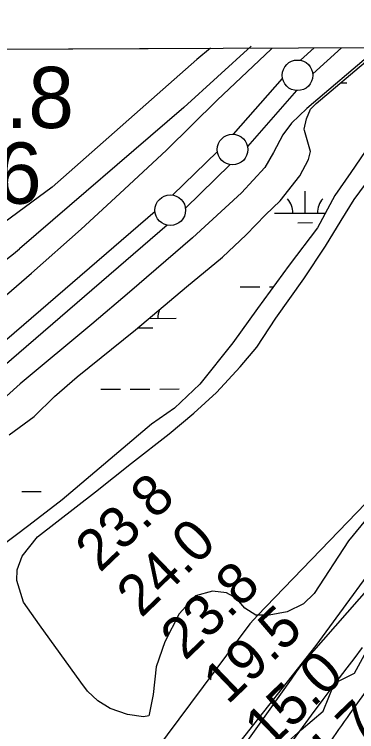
# Model space of a CAD drawing. Extents: x 3424494 to 3462436, y 522220 to 547718.
# Drawn here: x 3447583 to 3448142, y 544764 to 545936 of the extents above; entities that cross this region are included whole.
import ezdxf

# ---------------------------------------------------------------- set-up
doc = ezdxf.new("R2010")
doc.units = 0
for name, color, linetype in [('V-GRID-FRAM', 7, 'Continuous'), ('V-LEVE-TOET', 7, 'Continuous'), ('V-RIVR-EDGE', 7, 'Continuous'), ('V-RIVR-RANG', 7, 'Continuous'), ('V-ROAD-CNTR', 7, 'Continuous'), ('V-SITE-VEGE', 7, 'Continuous'), ('V-SURV-IDEN', 7, 'Continuous'), ('V-SURV-LINE', 7, 'Continuous'), ('V-TOPO-DPTH', 7, 'Continuous'), ('V-TOPO-MINR', 7, 'Continuous'), ('V-WETL-SWMP', 7, 'Continuous')]:
    doc.layers.add(name, color=color, linetype=linetype)

msp = doc.modelspace()

# ---------------------------------------------------------------- linework, layer by layer
at = {"layer": 'V-GRID-FRAM'}
for points in [[(3428547.8, 545793.2), (3460200.7, 545935.9)], [(3428547.8, 545793.2), (3451467.1, 545896.5)]]:
    msp.add_lwpolyline(points, dxfattribs=at)
at = {"layer": 'V-LEVE-TOET'}
for points in [[(3446734.1, 544761.9), (3446808.8, 544826.2), (3446895.8, 544902.1), (3446976.1, 544971.6), (3447070.3, 545048.6), (3447166.5, 545134), (3447247.2, 545207.1), (3447327, 545278.2), (3447384.7, 545328.2), (3447416.5, 545354), (3447439.5, 545375.9), (3447451.8, 545384.6), (3447464.5, 545393.7), (3447537.3, 545449.3), (3447610.8, 545513.3), (3447692.3, 545585.1), (3447755.1, 545643.5), (3447831.4, 545714.2), (3447914, 545795.6), (3448001.9, 545879), (3448003.7, 545880.9)], [(3448177, 545881.7), (3448171.9, 545876.8), (3448060.2, 545782.3), (3448035.6, 545758.1), (3448021.3, 545739), (3448005.8, 545710.4), (3447991.9, 545685.8), (3447953.7, 545644.5), (3447873.8, 545571), (3447770.9, 545482), (3447709.3, 545429.6), (3447592.4, 545332.3), (3447519.7, 545267.2), (3447440.2, 545198.9), (3447431.5, 545190.1), (3447416.4, 545175.4), (3447410.4, 545170.3), (3447402.1, 545163.9), (3447381.8, 545146.8), (3447242.3, 545026.9), (3447093.7, 544898.2), (3446965.7, 544788.2), (3446817.5, 544663.1)]]:
    msp.add_lwpolyline(points, dxfattribs=at)
at = {"layer": 'V-RIVR-EDGE'}
msp.add_spline([(3449024.5, 545885.5), (3449019.3, 545873.5), (3449011.8, 545864), (3448999, 545850.5), (3448985, 545836.1), (3448976.3, 545824.5), (3448965.5, 545808.1), (3448951.4, 545790.8), (3448930.4, 545766.9), (3448908.8, 545733.6), (3448893.9, 545712.1), (3448877.4, 545692), (3448858.8, 545671.4), (3448838.9, 545650.8), (3448829.8, 545641), (3448822, 545628.2), (3448802.1, 545605.2), (3448785.1, 545578.4), (3448774, 545564.8), (3448769, 545560.7), (3448761.1, 545553.7), (3448753.7, 545540.1), (3448748.7, 545530.6), (3448741.3, 545522), (3448732.6, 545514.6), (3448730.5, 545510.9), (3448729.7, 545504.3), (3448730.5, 545498.5), (3448726.4, 545491.9), (3448714, 545480.8), (3448695.8, 545464.4), (3448686.3, 545455.7), (3448680.1, 545452.4), (3448668.5, 545431.4), (3448642, 545397.3), (3448623, 545372.2), (3448598.5, 545341.7), (3448586.1, 545326.9), (3448567.5, 545299.7), (3448554.3, 545276.7), (3448543.5, 545261), (3448535.2, 545255.3), (3448529.4, 545249.1), (3448514.6, 545229.3), (3448492.2, 545191.9), (3448480.6, 545178.7), (3448457.5, 545153.6), (3448442.1, 545135.1), (3448424.4, 545110.8), (3448410.3, 545090.6), (3448392.9, 545075.8), (3448377.6, 545060.6), (3448361.1, 545040.4), (3448350.7, 545027.7), (3448339.1, 545005.8), (3448331.3, 544993.5), (3448317.6, 544978.7), (3448303.6, 544960.5), (3448289.9, 544948.2), (3448280, 544931.7), (3448265.1, 544908.3), (3448249.8, 544884), (3448245.2, 544876.6), (3448244.4, 544872.9), (3448244.4, 544867.1), (3448242.3, 544863.4), (3448237.7, 544861.3), (3448234.4, 544856.8), (3448231.1, 544846.5), (3448224.9, 544842), (3448220.4, 544838.3), (3448221.6, 544830.8), (3448219.1, 544824.3), (3448214.5, 544819.7), (3448208.8, 544818.9), (3448205.5, 544816.4), (3448194.7, 544800.4), (3448196.4, 544802), (3448189.7, 544791.3), (3448179.4, 544775.7), (3448174, 544768.7), (3448167.4, 544757.2), (3448157.4, 544744.4), (3448145.4, 544730.8), (3448135.1, 544715.2), (3448124.8, 544701.2), (3448119.4, 544699.9), (3448113.2, 544693), (3448107.4, 544682.7), (3448106.1, 544678.9), (3448100.3, 544665.8), (3448092.9, 544652.2), (3448086.3, 544642.3), (3448078.8, 544638.2), (3448075.5, 544633.2), (3448067.2, 544618.8), (3448046.1, 544585.9), (3448037.4, 544569.4), (3448028.3, 544560.4), (3448024.6, 544560), (3448021.7, 544557.1), (3448012.6, 544541.4), (3448005.1, 544530.7), (3447995.6, 544524.6), (3447994.8, 544522.1), (3447994.4, 544515.5), (3447992.3, 544513.4), (3447987, 544513), (3447986.9, 544505.6), (3447985.7, 544501.9), (3447978.3, 544497.8), (3447969.6, 544490), (3447961.3, 544476.4), (3447954.7, 544466.9), (3447950.1, 544453.7), (3447948, 544444.7), (3447946.4, 544440.1), (3447940.2, 544435.2), (3447932.3, 544427.8), (3447921.6, 544414.6), (3447905.4, 544390.8), (3447884.7, 544360.7), (3447854.9, 544322.4), (3447838, 544301.8), (3447830.9, 544294), (3447828, 544286.2), (3447823.9, 544273.8), (3447817.7, 544265.2), (3447807.7, 544251.6), (3447798.6, 544239.7), (3447792, 544235.1), (3447787.5, 544230.2), (3447785.4, 544227.7), (3447783.7, 544218.3), (3447781.7, 544216.2), (3447776.3, 544210.9), (3447766.4, 544194.8), (3447753.1, 544178.7), (3447722.9, 544136.3), (3447707.6, 544119.1), (3447694.8, 544104.2), (3447681.1, 544084.1), (3447673.7, 544073.8), (3447667, 544060.6), (3447657.1, 544050.3), (3447653.8, 544047.4), (3447652.2, 544044.1), (3447650.1, 544037.5), (3447645.5, 544031.8), (3447640.2, 544026.8), (3447633.1, 544020.3), (3447624.9, 544014.5), (3447616.6, 544013.7), (3447613.3, 544010), (3447605, 544000.9), (3447598.8, 543989), (3447590.1, 543972.9), (3447575.6, 543949.5), (3447562.4, 543928.5), (3447550.8, 543912), (3447539.6, 543898), (3447530.9, 543888.1), (3447527.6, 543882.8), (3447525.5, 543874.1), (3447521.8, 543870.4), (3447516, 543864.7), (3447515.2, 543861), (3447514.8, 543854.8), (3447509.8, 543851.1), (3447503.2, 543848.2), (3447495.3, 543829.7), (3447484.6, 543819), (3447471.8, 543804.1), (3447462.7, 543795.1), (3447454, 543781.9), (3447440.3, 543762.2), (3447430.4, 543746.5), (3447426.2, 543740.3), (3447424.1, 543732.1), (3447421.7, 543729.2), (3447414.2, 543721.8), (3447406, 543717.3), (3447398.5, 543709.9), (3447394, 543701.2), (3447391.1, 543696.3), (3447384, 543692.2), (3447379.5, 543687.7), (3447373.7, 543676.1), (3447366.2, 543663.8), (3447360.4, 543649.4), (3447357.9, 543636.6), (3447352.5, 543628.8), (3447345.1, 543626.7), (3447341.4, 543623), (3447336.4, 543618.5), (3447328.2, 543607.8), (3447317, 543591.3), (3447306.2, 543572.8), (3447293.8, 543548.9), (3447283.4, 543532), (3447267.3, 543508.1), (3447258.6, 543503.6), (3447254.1, 543498.7), (3447252, 543493.7), (3447247.4, 543485.9), (3447242.1, 543476.8), (3447234.2, 543467), (3447228.4, 543461.6), (3447225.1, 543458.3), (3447223.9, 543452.6), (3447222.6, 543443.9), (3447217.6, 543437.3), (3447211, 543429.9), (3447197.4, 543418.4), (3447193.6, 543413), (3447188.7, 543405.6), (3447177.5, 543390.8), (3447165.1, 543376), (3447155.2, 543362), (3447143.6, 543347.6), (3447132.4, 543332), (3447125.4, 543325.4), (3447119.6, 543316.7), (3447107.2, 543302.3), (3447099.3, 543290), (3447082.4, 543268.2), (3447069.5, 543250.5), (3447056.7, 543231.5), (3447044.7, 543214.2), (3447030.6, 543189.1), (3447016.9, 543167.7), (3447008.7, 543152), (3446997.5, 543133.1), (3446988.4, 543122.4), (3446978.9, 543109.6), (3446965.6, 543092.3), (3446951.1, 543073), (3446946.6, 543071.8), (3446942.5, 543067.7), (3446932.1, 543057), (3446914.3, 543030.2)], degree=3, dxfattribs=at)
at = {"layer": 'V-ROAD-CNTR'}
msp.add_lwpolyline([(3447969.6, 545884), (3447859.6, 545783.8), (3447591.3, 545552.7)], dxfattribs=at)
msp.add_arc((3447311.7, 545880.9), 431.2, 257.7647, 310.4335, dxfattribs=at)
at = {"layer": 'V-SITE-VEGE'}
for p, q in [((3447319.9, 545877.8), (3447902.9, 545880.4)), ((3447902.9, 545880.4), (3447881.1, 545862.3)), ((3447881.1, 545862.3), (3447644.5, 545653.4)), ((3448137.8, 545633.7), (3448163.7, 545669.1)), ((3447644.5, 545653.4), (3447546.2, 545581.1)), ((3448116.5, 545599.1), (3448137.8, 545633.7)), ((3448090.6, 545557.4), (3448116.5, 545599.1)), ((3448055.2, 545503.9), (3448090.6, 545557.4)), ((3448009.5, 545439.5), (3448055.2, 545503.9)), ((3447978.8, 545392.3), (3448009.5, 545439.5)), ((3447951.3, 545360.1), (3447978.8, 545392.3)), ((3447912.8, 545318.4), (3447951.3, 545360.1)), ((3447875.8, 545284.6), (3447912.8, 545318.4)), ((3447835.7, 545250.8), (3447875.8, 545284.6)), ((3447774.3, 545202.8), (3447835.7, 545250.8)), ((3447715.3, 545155.7), (3447774.3, 545202.8)), ((3447620.9, 545082.6), (3447715.3, 545155.7)), ((3448161.2, 545115.4), (3448128.1, 545076.1)), ((3447595.7, 545051.1), (3447620.9, 545082.6)), ((3448128.1, 545076.1), (3448072.3, 544989.6)), ((3447587.9, 545028.3), (3447595.7, 545051.1)), ((3447587.1, 545011), (3447587.9, 545028.3)), ((3447598.1, 544975.6), (3447587.1, 545011)), ((3447906.3, 544993.6), (3447878.8, 544985.8)), ((3447929.2, 544991.2), (3447906.3, 544993.6)), ((3447940.2, 544984.9), (3447929.2, 544991.2)), ((3447878.8, 544985.8), (3447852.1, 544956.7)), ((3447949.6, 544977.1), (3447940.2, 544984.9)), ((3448072.3, 544989.6), (3448055, 544973.1)), ((3447624, 544938.7), (3447598.1, 544975.6)), ((3447959, 544966.1), (3447949.6, 544977.1)), ((3448055, 544973.1), (3448028.2, 544959.7)), ((3447852.1, 544956.7), (3447828.5, 544911.1)), ((3447977.1, 544954.3), (3447959, 544966.1)), ((3448028.2, 544959.7), (3447999.1, 544954.2)), ((3447999.1, 544954.2), (3447977.1, 544954.3)), ((3447691.6, 544845), (3447624, 544938.7)), ((3447828.5, 544911.1), (3447814.3, 544870.2)), ((3447814.3, 544870.2), (3447809.6, 544824.6)), ((3447702.6, 544830.1), (3447691.6, 544845)), ((3447719.1, 544814.4), (3447702.6, 544830.1)), ((3447739.6, 544801.8), (3447719.1, 544814.4)), ((3447809.6, 544824.6), (3447803.3, 544792.3)), ((3447767.9, 544792.3), (3447739.6, 544801.8)), ((3447793.8, 544788.4), (3447767.9, 544792.3)), ((3447803.3, 544792.3), (3447802.5, 544790)), ((3447802.5, 544790), (3447793.8, 544788.4))]:
    msp.add_line(p, q, dxfattribs=at)
for points in [[(3448902.8, 545885), (3448856.5, 545884.7), (3448648.2, 545628.3), (3448471.8, 545429.8), (3448207.3, 545085.7), (3448075, 544904.8), (3447942.8, 544737.2)], [(3447998.2, 544719.9), (3448051.3, 544767.3), (3448087.2, 544797.4), (3448105.7, 544843.6), (3448138, 544859.8), (3448161.2, 544901.4), (3448193.3, 544966.8), (3448305.4, 545102.1), (3448366.7, 545187.6), (3448419.9, 545248.9), (3448451.1, 545275.5), (3448485.7, 545314.8), (3448496.1, 545348.4), (3448544.7, 545391.2), (3448565.5, 545424.7), (3448532, 545459.4), (3448581.7, 545489.5), (3448658.9, 545540), (3448681.3, 545564.2), (3448709, 545611.8), (3448873.2, 545805.4), (3448901.6, 545882.9), (3448902.8, 545885)]]:
    msp.add_lwpolyline(points, dxfattribs=at)
at = {"layer": 'V-SURV-LINE'}
for points in [[(3448049.9, 545860.9), (3448072.1, 545881.2)], [(3448116.8, 545881.4), (3448070.1, 545838.7)], [(3447940.9, 545740), (3448020.8, 545831.2)], [(3448043.3, 545811.4), (3447963.5, 545720.2)], [(3447841.3, 545640.7), (3447914.3, 545711.9)], [(3447935.2, 545690.4), (3447862.3, 545619.2)], [(3445808.1, 543883.4), (3447812.6, 545614.3)], [(3447832.2, 545591.6), (3445827.7, 543860.7)]]:
    msp.add_lwpolyline(points, dxfattribs=at)
for centre in [(3448045.2, 545836.3), (3447939.1, 545715.1), (3447837.5, 545616)]:
    msp.add_circle(centre, 25, dxfattribs=at)
at = {"layer": 'V-TOPO-DPTH'}
msp.add_lwpolyline([(3448150.6, 544901.5), (3448136.8, 544883.2), (3448125.6, 544868.3), (3448106.1, 544842.6), (3448086.7, 544816.8), (3448067.5, 544790.9), (3448048.3, 544764.9), (3447974.6, 544664.4)], dxfattribs=at)
at = {"layer": 'V-TOPO-MINR'}
for points in [[(3448838.6, 545884.7), (3448672, 545671), (3448597.4, 545587.7), (3448583.1, 545572), (3448568.7, 545556.4), (3448554, 545541.1), (3448539.2, 545525.9), (3448405.8, 545391.8), (3448332, 545317.3), (3448258.4, 545242.5), (3448185.3, 545167.3), (3448112.4, 545091.9), (3447993.5, 544968.3), (3447980.3, 544954.4), (3447967.4, 544940.5), (3447485.7, 544294.2)], [(3448918.4, 545885), (3448905.8, 545869.2), (3448845.5, 545794.2), (3448784.7, 545719.4), (3448659.8, 545566.8), (3448654.4, 545560.2), (3448648.9, 545553.7), (3448643.3, 545547.2), (3448637.8, 545540.7), (3448634, 545536.4), (3448630.2, 545532.2), (3448626.5, 545528), (3448622.7, 545523.8), (3448618.9, 545519.6), (3448613.8, 545514.2), (3448612.5, 545512.8), (3448609.9, 545510), (3448608.6, 545508.6), (3448051.7, 544873.9), (3448043.1, 544862.1), (3448034.7, 544850.1), (3447859, 544602.8)], [(3448216.9, 544913.9), (3448130.6, 544794), (3448126, 544787.4), (3448121.3, 544780.9), (3448116.8, 544774.3), (3448112.2, 544767.7), (3448099.7, 544749.3)], [(3448150.6, 544901.5), (3448136.8, 544883.2), (3448125.6, 544868.3), (3448106.1, 544842.6), (3448086.7, 544816.8), (3448067.5, 544790.9), (3448048.3, 544764.9), (3447974.6, 544664.4)]]:
    msp.add_lwpolyline(points, dxfattribs=at)
at = {"layer": 'V-WETL-SWMP'}
for p, q in [((3448075.7, 545790.2), (3448163, 545864.1)), ((3448115.6, 545824), (3448125.9, 545824)), ((3448066.3, 545780.8), (3448075.7, 545790.2)), ((3448060, 545765), (3448066.3, 545780.8)), ((3448056, 545748.5), (3448060, 545765)), ((3448056.8, 545746.2), (3448056, 545748.5)), ((3448066.2, 545711.6), (3448056.8, 545746.2)), ((3448163.8, 545724.1), (3448132.3, 545677.7)), ((3448063.1, 545699), (3448066.2, 545711.6)), ((3448048.9, 545672.2), (3448063.1, 545699)), ((3448016.7, 545631.4), (3448048.9, 545672.2)), ((3448132.3, 545677.7), (3448106.3, 545640)), ((3448057.7, 545611.1), (3448057.6, 545647.1)), ((3448106.3, 545640), (3448078, 545587.3)), ((3447993.1, 545608.6), (3448016.7, 545631.4)), ((3448007.7, 545610.9), (3448090.9, 545611.3)), ((3447961.6, 545575.5), (3447993.1, 545608.6)), ((3448078, 545587.3), (3448031.6, 545526)), ((3448045.8, 545595.6), (3448069.8, 545595.8)), ((3447923, 545539.4), (3447961.6, 545575.5)), ((3447864.1, 545490.6), (3447923, 545539.4)), ((3448031.6, 545526), (3447979.6, 545455.2)), ((3447780.7, 545420.7), (3447864.1, 545490.6)), ((3447951.4, 545490.6), (3447983.4, 545490.7)), ((3447999.4, 545490.8), (3448005.8, 545490.8)), ((3447979.6, 545455.2), (3447939.5, 545399.4)), ((3447802.7, 545439.2), (3447847.1, 545439.4)), ((3447785.2, 545423.7), (3447809.2, 545423.8)), ((3447685.5, 545343.6), (3447780.7, 545420.7)), ((3447939.5, 545399.4), (3447886, 545331.8)), ((3447648.5, 545311.4), (3447685.5, 545343.6)), ((3447886, 545331.8), (3447844.3, 545292.5)), ((3447724.2, 545323.4), (3447756.2, 545323.5)), ((3447772.2, 545323.6), (3447804.2, 545323.7)), ((3447820.2, 545323.8), (3447852.2, 545324)), ((3447615.5, 545279.2), (3447648.5, 545311.4)), ((3447844.3, 545292.5), (3447806.6, 545266.5)), ((3447574.6, 545249.3), (3447615.5, 545279.2)), ((3447806.6, 545266.5), (3447661, 545143.1)), ((3447595, 545156.3), (3447627, 545156.4)), ((3447661, 545143.1), (3447606.8, 545100.7)), ((3447606.8, 545100.7), (3447559.6, 545065.3))]:
    msp.add_line(p, q, dxfattribs=at)
for centre, start, end in [((3448002.5, 545611.4), 359.4865, 41.0302), ((3448113, 545611.9), 139.4865, 181.0302), ((3447852.3, 545439.9), 157.1727, 181.0302)]:
    msp.add_arc(centre, 35.2, start, end, dxfattribs=at)

# ---------------------------------------------------------------- texts
at = {"layer": 'V-RIVR-RANG'}
for s, p in [('23.8', (3447722.8, 545022.8)), ('24.0', (3447790.1, 544948.8)), ('23.8', (3447861.7, 544878.9)), ('19.5', (3447931.1, 544806.9)), ('15.0', (3447998.4, 544733)), ('4.7', (3448094, 544686))]:
    msp.add_text(s, height=67, rotation=43.8383, dxfattribs=at).set_placement(p)
at = {"layer": 'V-SURV-IDEN'}
for s, rotation, p in [('3757+80.8', 359.6877, (3447044.2, 545753.4)), ('3756+19.6', 359.0459, (3446991.3, 545636.6))]:
    msp.add_text(s, height=100, rotation=rotation, dxfattribs=at).set_placement(p)

doc.saveas('drawing.dxf')
